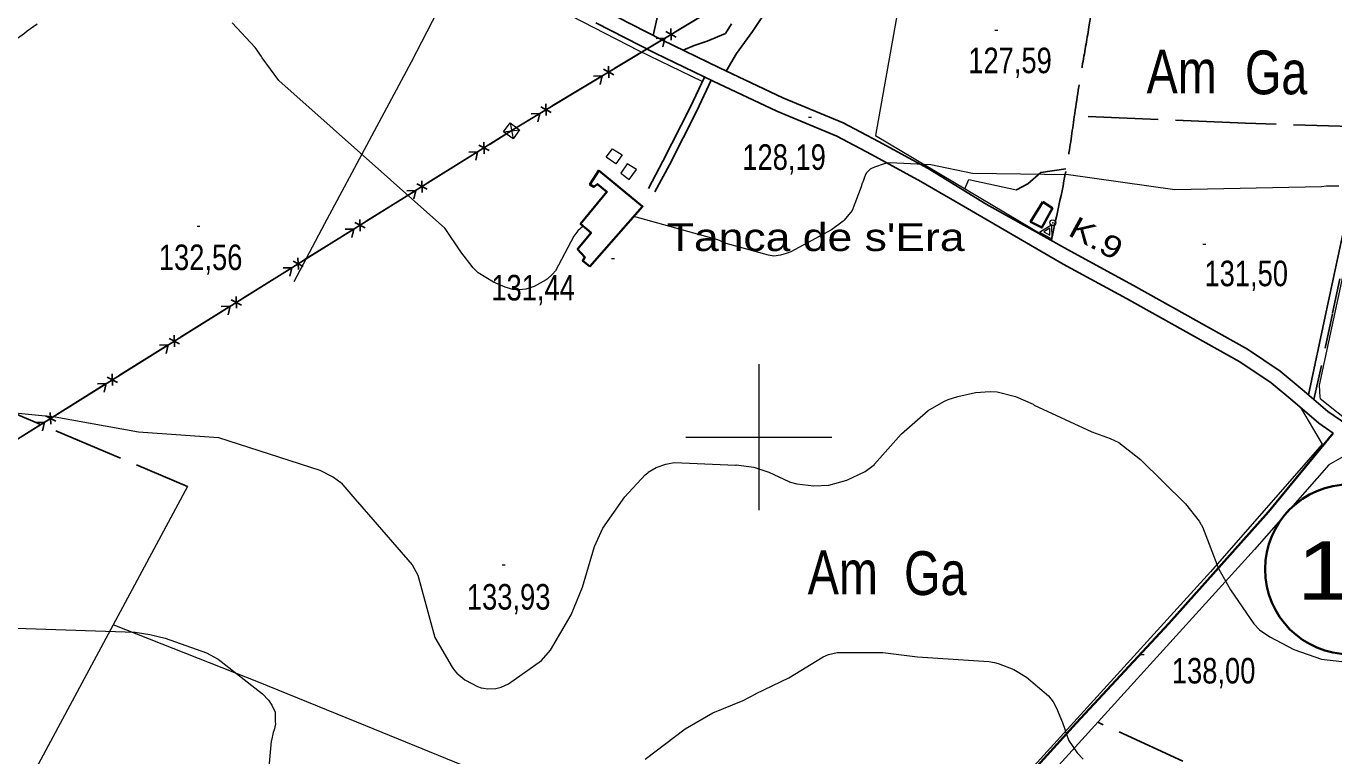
# Model space of a CAD drawing. Extents: x 483840 to 488445, y 4386047 to 4389027.
# Drawn here: x 484749 to 485197, y 4386890.9 to 4387140.8 of the extents above; entities that cross this region are included whole.
import ezdxf
from ezdxf.enums import TextEntityAlignment as Align

# ---------------------------------------------------------------- set-up
doc = ezdxf.new("R2010")
doc.units = 0
doc.header["$LTSCALE"] = 4
doc.header["$PDMODE"] = 32
doc.header["$PDSIZE"] = 2
doc.linetypes.add('LONG_DASHED', pattern=[7.5, 6, -1.5])
doc.linetypes.add('MEDIUM_DASHED', pattern=[4.5, 3, -1.5])
for name, color, linetype, lineweight in [('1', 7, 'Continuous', 13), ('13', 7, 'Continuous', 25), ('25', 7, 'LONG_DASHED', 25), ('36', 7, 'Continuous', 25), ('38', 7, 'Continuous', 25), ('41', 7, 'Continuous', 13), ('43', 7, 'Continuous', 25), ('47', 7, 'Continuous', 35), ('51', 7, 'Continuous', 13), ('6', 7, 'Continuous', 35), ('7', 7, 'Continuous', 13), ('9', 7, 'Continuous', 13)]:
    doc.layers.add(name, color=color, linetype=linetype, lineweight=lineweight)
doc.layers.add('31', color=7, linetype='Continuous')
doc.layers.add('5', color=7, linetype='Continuous')

msp = doc.modelspace()

# ---------------------------------------------------------------- linework, layer by layer
at = {"layer": '1'}
for p, q in [((485000, 4387025), (485000, 4386975)), ((484975, 4387000), (485025, 4387000))]:
    msp.add_line(p, q, dxfattribs=at)
at = {"layer": '25'}
for points in [[(484963.78, 4387137.66), (484966.84, 4387151.33), (484970.05, 4387166.71), (484972.16, 4387181.4)], [(484988.82, 4387125.45), (484992.36, 4387131.49), (484997.83, 4387138.95), (485003.57, 4387147.66)], [(484990.57, 4387141.65), (484988.59, 4387138.3), (484982.27, 4387135.64), (484977.77, 4387134.25), (484974.08, 4387132.58)], [(485207.15, 4387106.31), (485166.73, 4387107.6), (485108.1, 4387110.1)], [(485088.22, 4387084.75), (485092.08, 4387086.8), (485096.56, 4387090.65), (485105.19, 4387091.9)], [(484605.65, 4387064.8), (484636.07, 4387053.26), (484682.07, 4387035.03), (484703.85, 4387025.51), (484804.18, 4386983.14)], [(485271.63, 4386833.7), (485227.54, 4386852.71), (485172.46, 4386876.52), (485116.08, 4386902.39)]]:
    msp.add_lwpolyline(points, dxfattribs=at)
at = {"layer": '36'}
for points in [[(484946.46, 4387146.48), (484966.73, 4387136.15), (484986.51, 4387126.53), (485008.19, 4387116.3), (485028.83, 4387107.68), (485040.94, 4387101.32), (485057.93, 4387092.09), (485077.85, 4387079.8), (485106.7, 4387063.72), (485128.35, 4387052.02), (485167.37, 4387030.13), (485178.54, 4387022.69), (485186.13, 4387016.32), (485194.95, 4387008.84), (485199.56, 4387005.59), (485207.95, 4386999.32), (485214.97, 4386994.81), (485222.72, 4386990.21), (485248.09, 4386976.31), (485288.29, 4386954.73), (485348.62, 4386921.76), (485417.64, 4386885.14), (485448.2, 4386871.57)], [(484944.1, 4387141.99), (484964.47, 4387131.61), (484984.32, 4387121.95), (485006.12, 4387111.66), (485026.67, 4387103.08), (485038.55, 4387096.84), (485055.45, 4387087.66), (485071.49, 4387078.37), (485104.22, 4387059.29), (485125.9, 4387047.57), (485164.72, 4387025.8), (485175.49, 4387018.62), (485182.86, 4387012.44), (485191.84, 4387004.83), (485196.68, 4387001.41)]]:
    msp.add_lwpolyline(points, dxfattribs=at)
at = {"layer": '38'}
for points in [[(485188.25, 4387014.54), (485194.36, 4387043), (485201.48, 4387076.51), (485208.39, 4387112.85), (485214.45, 4387136.72), (485216.2, 4387147.63), (485220.52, 4387164.1), (485225.14, 4387190.18), (485225.46, 4387192.5), (485227, 4387196.19), (485229.51, 4387198.81), (485232.3, 4387200), (485239.48, 4387200.37), (485243.82, 4387199.78), (485254.95, 4387197.29), (485284.57, 4387190.75), (485297.27, 4387187.95), (485301.83, 4387187.79), (485305.79, 4387188.48), (485308.4, 4387189.83), (485311.39, 4387192.48), (485316.45, 4387198.49)], [(484981.35, 4387123.4), (484976.44, 4387112.92), (484967.13, 4387094.52), (484962.12, 4387085.23)], [(484983.61, 4387122.28), (484978.71, 4387111.82), (484969.37, 4387093.35), (484964.34, 4387084.03)]]:
    msp.add_lwpolyline(points, dxfattribs=at)
at = {"layer": '38', "linetype": 'MEDIUM_DASHED'}
msp.add_lwpolyline([(485190.16, 4387012.9), (485196.52, 4387042.53), (485203.65, 4387076.07), (485210.55, 4387112.37), (485216.62, 4387136.27), (485218.37, 4387147.17), (485222.68, 4387163.62), (485227.32, 4387189.84), (485227.61, 4387191.91), (485228.88, 4387194.97), (485230.78, 4387196.96), (485232.81, 4387197.81), (485239.39, 4387198.15), (485243.43, 4387197.6), (485254.47, 4387195.13), (485284.09, 4387188.59), (485297, 4387185.75), (485301.98, 4387185.57), (485306.51, 4387186.37), (485309.65, 4387188), (485312.97, 4387190.93), (485318.14, 4387197.07)], dxfattribs=at)
at = {"layer": '38', "linetype": 'LONG_DASHED'}
msp.add_spline([(485100.14, 4387067.55), (485105.76, 4387094.65), (485108.05, 4387109.75), (485110.91, 4387128.01), (485113.17, 4387141.29), (485116.07, 4387161.02), (485118.64, 4387174.55), (485120.17, 4387182.77)], degree=3, dxfattribs=at)
at = {"layer": '41'}
for p, q in [((485096.09, 4387070.3), (485100.36, 4387072.9)), ((485100.48, 4387067.9), (485100.36, 4387072.9)), ((485096.09, 4387070.3), (485100.48, 4387067.9))]:
    msp.add_line(p, q, dxfattribs=at)
msp.add_lwpolyline([(485099.64, 4387071.58), (485097.59, 4387070.33), (485099.7, 4387069.18)], close=True, dxfattribs=at)
msp.add_point((485100.68, 4387073.49), dxfattribs=at)
at = {"layer": '43'}
for p, q in [((484972.05, 4387139.28), (484989.18, 4387149.6)), ((484971.66, 4387137.02), (484968.16, 4387138.95)), ((484969.95, 4387135.99), (484969.87, 4387139.98)), ((484950.63, 4387126.38), (484967.76, 4387136.7)), ((484967.76, 4387136.7), (484964.76, 4387136.64)), ((484967.76, 4387136.7), (484967.04, 4387133.79)), ((484950.25, 4387124.11), (484946.75, 4387126.05)), ((484948.53, 4387123.08), (484948.46, 4387127.08)), ((484929.22, 4387113.48), (484946.35, 4387123.8)), ((484946.35, 4387123.8), (484943.35, 4387123.74)), ((484946.35, 4387123.8), (484945.63, 4387120.89)), ((484928.83, 4387111.21), (484925.33, 4387113.14)), ((484927.12, 4387110.18), (484927.05, 4387114.17)), ((484924.94, 4387110.9), (484921.94, 4387110.84)), ((484924.94, 4387110.9), (484924.22, 4387107.99)), ((484886.67, 4387087.22), (484903.64, 4387097.81)), ((484903.64, 4387097.81), (484900.64, 4387097.7)), ((484903.64, 4387097.81), (484902.96, 4387094.89)), ((484907.53, 4387098.18), (484904, 4387100.06)), ((484905.83, 4387097.12), (484905.7, 4387101.12)), ((484865.47, 4387073.98), (484882.43, 4387084.57)), ((484882.43, 4387084.57), (484879.43, 4387084.46)), ((484882.43, 4387084.57), (484881.76, 4387081.65)), ((484886.32, 4387084.95), (484882.79, 4387086.82)), ((484884.63, 4387083.89), (484884.49, 4387087.88)), ((484844.26, 4387060.74), (484861.22, 4387071.33)), ((484861.22, 4387071.33), (484858.22, 4387071.23)), ((484861.22, 4387071.33), (484860.55, 4387068.41)), ((484865.11, 4387071.71), (484861.59, 4387073.58)), ((484863.42, 4387070.65), (484863.28, 4387074.64)), ((484823.05, 4387047.5), (484840.02, 4387058.09)), ((484840.02, 4387058.09), (484837.02, 4387057.99)), ((484840.02, 4387058.09), (484839.34, 4387055.17)), ((484843.91, 4387058.47), (484840.38, 4387060.35)), ((484842.21, 4387057.41), (484842.07, 4387061.41)), ((484801.84, 4387034.26), (484818.81, 4387044.86)), ((484818.81, 4387044.86), (484815.81, 4387044.75)), ((484818.81, 4387044.86), (484818.13, 4387041.93)), ((484822.7, 4387045.23), (484819.17, 4387047.11)), ((484821, 4387044.17), (484820.87, 4387048.17)), ((484780.64, 4387021.03), (484797.6, 4387031.62)), ((484797.6, 4387031.62), (484794.6, 4387031.51)), ((484797.6, 4387031.62), (484796.93, 4387028.7)), ((484801.49, 4387031.99), (484797.96, 4387033.87)), ((484799.8, 4387030.94), (484799.66, 4387034.93)), ((484778.59, 4387017.7), (484778.45, 4387021.69)), ((484759.43, 4387007.79), (484776.39, 4387018.38)), ((484776.39, 4387018.38), (484773.39, 4387018.28)), ((484776.39, 4387018.38), (484775.72, 4387015.46)), ((484780.28, 4387018.76), (484776.76, 4387020.63)), ((484757.38, 4387004.46), (484757.24, 4387008.45)), ((484738.22, 4386994.55), (484755.19, 4387005.14)), ((484755.19, 4387005.14), (484752.19, 4387005.04)), ((484755.19, 4387005.14), (484754.51, 4387002.22)), ((484759.08, 4387005.52), (484755.55, 4387007.39))]:
    msp.add_line(p, q, dxfattribs=at)
at = {"layer": '43', "lineweight": 13}
for p, q in [((484914.77, 4387107.66), (484915.79, 4387102.22)), ((484912.53, 4387104.61), (484918.03, 4387105.27))]:
    msp.add_line(p, q, dxfattribs=at)
at = {"layer": '43'}
for points in [[(484653.39, 4386941.6), (484915.42, 4387105.16), (485163.22, 4387254.48)], [(484907.88, 4387100.45), (484915.42, 4387105.16), (484924.94, 4387110.9)]]:
    msp.add_lwpolyline(points, dxfattribs=at)
at = {"layer": '43', "lineweight": 13}
msp.add_lwpolyline([(484912.53, 4387104.61), (484914.77, 4387107.66), (484918.03, 4387105.27), (484915.79, 4387102.22)], close=True, dxfattribs=at)
at = {"layer": '47', "lineweight": 13}
for points in [[(484953.18, 4387096.71), (484950.94, 4387093.68), (484947.63, 4387095.98), (484949.88, 4387098.83)], [(484954.89, 4387093.66), (484952.68, 4387090.48), (484955.54, 4387088.3), (484958.06, 4387091.76)]]:
    msp.add_lwpolyline(points, close=True, dxfattribs=at)
at = {"layer": '47'}
for points in [[(484942.04, 4387058.44), (484939.67, 4387060.44), (484940.35, 4387061.73), (484937.87, 4387064.48), (484942.48, 4387069.99), (484938.89, 4387073.08), (484947.92, 4387084.02), (484944.72, 4387086.73), (484943.48, 4387085.73), (484942.09, 4387086.58), (484945.12, 4387091.36), (484960.14, 4387079.02)], [(485097.24, 4387080.64), (485100.57, 4387078.42), (485096.97, 4387071.84), (485093.08, 4387073.8)]]:
    msp.add_lwpolyline(points, close=True, dxfattribs=at)
at = {"layer": '51'}
for points in [[(485056.04, 4387197.31), (485048.18, 4387149.53), (485039.89, 4387103.37), (485097.76, 4387068.96)], [(484980.61, 4387121.81), (484958.86, 4387132.33), (484920.47, 4387152.2), (484898.75, 4387163.33), (484880.88, 4387128.52), (484851.17, 4387073.15), (484840.62, 4387053.24)], [(485211.83, 4387115.45), (485207.06, 4387090.98), (485199.89, 4387054.91), (485191.99, 4387017.86), (485192.19, 4387013.68), (485192.32, 4387013.27), (485204.03, 4387003.89), (485209.22, 4386999.27), (485215.35, 4386995.69), (485234.92, 4386984.21), (485275.53, 4386962.4), (485279.61, 4386964.02), (485308.69, 4386990), (485319.72, 4386999.72), (485317.17, 4387005.08), (485314.05, 4387009.54), (485313.72, 4387013.08), (485314.83, 4387020.32), (485318.55, 4387025.66), (485322.24, 4387030.53), (485324.33, 4387033.56), (485324.78, 4387034.4), (485288.39, 4387062.04), (485256.64, 4387083.92)], [(485070.57, 4387085.14), (485071.87, 4387088.34), (485088.22, 4387084.75)], [(485185.57, 4387010.15), (485192.96, 4386997.58), (485154.71, 4386953.88), (485087.38, 4386879.83), (485039.97, 4386830.05), (485002.88, 4386794.18), (484978.66, 4386773.72)], [(485271.63, 4386833.7), (485336.91, 4386885.19), (485363.1, 4386905.52), (485314.95, 4386930.98), (485258.88, 4386961.46), (485200.79, 4386993.71), (485195.25, 4386990.5), (485169.73, 4386961.5), (485094.98, 4386879.15), (485094.05, 4386878.62)], [(484804.18, 4386983.14), (484753.23, 4386888.09), (484745.19, 4386872.4), (484715.09, 4386826.08), (484659.98, 4386740.02)], [(484917.58, 4386879.79), (484865.38, 4386901.2), (484828.54, 4386916.12), (484778.79, 4386935.76)]]:
    msp.add_lwpolyline(points, dxfattribs=at)
at = {"layer": '6'}
msp.add_lwpolyline([(485196.68, 4387001.41), (485174.53, 4386974.43), (485140.42, 4386936.16), (485108.67, 4386902.09), (485070.95, 4386860.47), (485042.96, 4386831.45), (485012.41, 4386802.17), (484984.19, 4386777.31), (484966.85, 4386762.96), (484954.68, 4386748.08), (484950.17, 4386739.57), (484953.68, 4386722.28), (484969.49, 4386709.51)], dxfattribs=at)
msp.add_circle((485202.52, 4386954.77), 29.1, dxfattribs=at)
at = {"layer": '7'}
for p, q in [((485080.84, 4387139.41), (485081.84, 4387139.41)), ((485017.01, 4387109.62), (485018.01, 4387109.62)), ((484807.51, 4387072.3), (484808.51, 4387072.3)), ((485152.13, 4387066.11), (485153.13, 4387066.11)), ((484949.52, 4387061.23), (484950.52, 4387061.23)), ((484912.04, 4386956.33), (484913.04, 4386956.33)), ((485130.96, 4386925.57), (485131.96, 4386925.57))]:
    msp.add_line(p, q, dxfattribs=at)
at = {"layer": '9'}
for points in [[(484752.7, 4387141.49), (484749.34, 4387139.13), (484748.44, 4387138.31), (484732.83, 4387127.4), (484725.79, 4387122.18), (484721.46, 4387117.78), (484721.35, 4387117.61), (484721.24, 4387117.35), (484720.82, 4387116.81), (484716.54, 4387112.69), (484714.16, 4387111.03), (484701.45, 4387104.13), (484689.43, 4387100.9), (484684.92, 4387100.31), (484681.75, 4387100.37), (484678.08, 4387100.97), (484676.91, 4387101.33), (484676.9, 4387101.34), (484676.89, 4387101.34), (484659.54, 4387108.58), (484659.51, 4387108.58), (484659.45, 4387108.63), (484658.92, 4387109.18), (484658.69, 4387109.49)], [(484939.79, 4387072.31), (484938, 4387070.72), (484936.59, 4387068.89), (484930.31, 4387056.99), (484929.33, 4387055.84), (484927.46, 4387054.16), (484927.12, 4387053.93), (484923.04, 4387051.69), (484920.14, 4387050.68), (484917.83, 4387050.45), (484917.63, 4387050.44), (484915.67, 4387050.65), (484913.04, 4387051.37), (484909.02, 4387053.09), (484903.84, 4387056.28), (484902.09, 4387058.03), (484897.91, 4387063.56), (484892.5, 4387071.54), (484892.44, 4387071.55), (484892.42, 4387071.55), (484892.39, 4387071.57), (484892.38, 4387071.6), (484892.38, 4387071.61), (484892.39, 4387071.66), (484835.51, 4387122.23), (484829.8, 4387129.93), (484829.58, 4387130.37), (484827.42, 4387133.53), (484819.5, 4387141.99)], [(485194.47, 4387085.99), (485192.68, 4387085.83), (485142.54, 4387084.74), (485106.1, 4387089.9), (485073.18, 4387090.38), (485058.93, 4387093.29), (485044.97, 4387094.04), (485042.92, 4387093.7), (485039.56, 4387092.55), (485039.34, 4387092.41), (485038.61, 4387092.09), (485038.16, 4387091.85), (485038.03, 4387091.76), (485037.37, 4387091.2), (485036.84, 4387090.52), (485036.55, 4387090.01), (485035.43, 4387087.14), (485035.41, 4387087.02), (485035.04, 4387085.75), (485031.95, 4387077.65), (485029.16, 4387074.35), (485028.83, 4387074.04), (485024.81, 4387071.1), (485010.97, 4387063.56), (485009.33, 4387062.9), (485007.35, 4387062.33), (485005.12, 4387062.08), (485003.32, 4387062.33), (484988.76, 4387066.42), (484985.91, 4387067.6), (484957.15, 4387075.63)], [(485198.71, 4387086.05), (485194.68, 4387086.04), (485194.47, 4387085.99)], [(485010.23, 4386984.88), (485010.33, 4386984.79), (485010.36, 4386984.78), (485012.95, 4386983.99), (485018.77, 4386983.34), (485023.93, 4386983.54), (485030.16, 4386985.34), (485036.35, 4386988.29), (485039.58, 4386990.72), (485039.59, 4386990.74), (485039.65, 4386990.82), (485048.75, 4387001.05), (485048.77, 4387001.05), (485048.78, 4387001.06), (485048.85, 4387001.13), (485048.86, 4387001.14), (485048.86, 4387001.16), (485058.03, 4387009.12), (485063.31, 4387012.24), (485064.88, 4387012.94), (485068.09, 4387013.97), (485074.25, 4387015.37), (485079.18, 4387015.68), (485081.65, 4387015.52), (485087.93, 4387013.98), (485093.94, 4387011.28), (485094.23, 4387011.1), (485094.31, 4387011.03), (485114.07, 4387001.83), (485120.33, 4386999.63), (485123.26, 4386998.25), (485130.76, 4386992.36), (485146.09, 4386977.24), (485150.8, 4386971.25), (485151.27, 4386970.47), (485151.34, 4386970.3), (485151.32, 4386970.27), (485151.32, 4386970.26), (485151.32, 4386970.24), (485151.34, 4386970.23), (485151.35, 4386970.22), (485151.39, 4386970.21), (485151.49, 4386970.07), (485151.91, 4386969.27), (485157.4, 4386955.01), (485161.61, 4386947.7), (485169.53, 4386936.1), (485171.48, 4386934.04), (485175, 4386931.61), (485183.22, 4386927.35), (485192.77, 4386923.97), (485224.64, 4386920.34)], [(484733.64, 4387009.53), (484758.85, 4387007.04), (484787.42, 4387001.88), (484814.8, 4386999.96), (484849.55, 4386988.78), (484854.26, 4386986.37), (484856.78, 4386984.45), (484856.97, 4386984.27), (484857.4, 4386983.75), (484862.27, 4386978.08), (484862.42, 4386977.86), (484881.23, 4386956.3), (484883.19, 4386952.78), (484888.99, 4386931.35), (484894.87, 4386921.3), (484895.7, 4386920.12), (484896.5, 4386919.17), (484899.29, 4386916.87), (484899.49, 4386916.74), (484903.59, 4386914.62), (484904.84, 4386914.2), (484905.65, 4386914.02), (484907.09, 4386913.87), (484909.84, 4386913.99), (484911.64, 4386914.39), (484914.18, 4386915.51), (484925.53, 4386923.58), (484928.59, 4386927.1), (484935.71, 4386939.19), (484939.57, 4386948.6), (484943.69, 4386962.56), (484946.49, 4386968.86), (484954.02, 4386979.59), (484961.07, 4386987.16), (484961.9, 4386987.85), (484962.06, 4386988), (484964.8, 4386989.63), (484968.12, 4386990.83), (484971.01, 4386991.39), (484991.97, 4386990.49), (484992.05, 4386990.47), (484992.07, 4386990.47), (484992.09, 4386990.47), (484992.15, 4386990.49), (484992.23, 4386990.55), (484998.27, 4386989.74), (485003.35, 4386988.07), (485010.23, 4386984.88)], [(484711.48, 4386935.75), (484786.25, 4386933.21), (484791.36, 4386932.45), (484796.57, 4386931.18), (484796.59, 4386931.17), (484810.75, 4386926.2), (484814.7, 4386923.94), (484829.89, 4386912.08), (484831.95, 4386909.92), (484833.14, 4386908.26), (484834.23, 4386905.79), (484834.32, 4386902.55), (484834.39, 4386901.88), (484834.07, 4386900.1), (484833.98, 4386899.78), (484833.62, 4386898.91), (484832.98, 4386896.17), (484832.95, 4386895.89), (484830.74, 4386871.79)], [(484961, 4386889.72), (484974.68, 4386900.07), (484984.26, 4386905.55), (484994.65, 4386909.84), (484998.97, 4386912.14), (484999.09, 4386912.22), (485010.27, 4386917.6), (485022.06, 4386924.75), (485023.85, 4386925.54), (485026.84, 4386926.3), (485042.42, 4386926.31), (485054.35, 4386924.75), (485078.73, 4386923.24), (485080.66, 4386922.9), (485082.02, 4386922.5), (485087.28, 4386920.49), (485087.35, 4386920.42), (485091.72, 4386917.84), (485099.22, 4386911.4), (485100.79, 4386909.35), (485101.98, 4386907.23), (485104.02, 4386902.3)], [(485104.02, 4386902.3), (485104.88, 4386899.65), (485104.87, 4386899.63), (485104.88, 4386899.53), (485106.03, 4386896.41), (485106.1, 4386896.27), (485108.98, 4386891.94), (485111.05, 4386889.71)]]:
    msp.add_lwpolyline(points, dxfattribs=at)

# ---------------------------------------------------------------- texts
at = {"layer": '13', "width": 1.25}
msp.add_text('10', height=20, dxfattribs=at).set_placement((485202.92, 4386944.35), align=Align.CENTER)
at = {"layer": '31', "width": 0.8}
for s, p in [('Am', (485144.84, 4387117.76)), ('Ga', (485177.2, 4387117.48)), ('Am', (485028.74, 4386946.22)), ('Ga', (485060.42, 4386945.95))]:
    msp.add_text(s, height=15, dxfattribs=at).set_placement(p, align=Align.CENTER)
at = {"layer": '41', "width": 1.25}
msp.add_text('K.9', height=7.5, rotation=331.411, dxfattribs=at).set_placement((485105.49, 4387069.39))
at = {"layer": '5', "width": 1.2}
msp.add_text("Tanca de s'Era", height=9.5, dxfattribs=at).set_placement((485070.47, 4387063.79), align=Align.RIGHT)
at = {"layer": '7', "width": 0.8}
for s, p in [('127,59', (485071.72, 4387124.71)), ('128,19', (484994.3, 4387091.6)), ('132,56', (484794.41, 4387057.27)), ('131,50', (485152.63, 4387051.74)), ('131,44', (484908.33, 4387046.86)), ('133,93', (484899.94, 4386940.96)), ('138,00', (485141.46, 4386915.65))]:
    msp.add_text(s, height=8.75, dxfattribs=at).set_placement(p)

doc.saveas('drawing.dxf')
